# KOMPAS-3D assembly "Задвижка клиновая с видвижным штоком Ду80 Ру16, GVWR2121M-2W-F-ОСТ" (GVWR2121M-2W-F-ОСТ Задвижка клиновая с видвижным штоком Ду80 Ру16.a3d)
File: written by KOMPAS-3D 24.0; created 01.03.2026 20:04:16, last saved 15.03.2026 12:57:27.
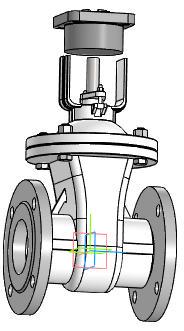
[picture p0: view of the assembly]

Document properties: Автор: R2D2; Полное имя файла: E:\Работа\Зайцев\GVWR2121M-2W-F-ОСТ Задвижка клиновая с видвижным штоком Ду50-300 Ру16\DN80\Исходные материалы\GVWR2121M-2W-F-ОСТ Задвижка клиновая с видвижным штоком Ду80 Ру16.a3d

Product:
- Component [detail]: AS 1110 - M12 x 45  | qty 4  | pos. 2  | Масса: 0.056439; Комментарий: Болты и винты   шестигранные точные   метрические ISO; Автор: R2D2; additional columns: Сталь, мягкая; source file: AS 1110 - M12 x 45 AS 1110 - M12 x 45.m3d
- Component [detail]: ANSI B18.2.4.2M - M12x1,75 - 18  | designation ANSI B18.2.4.2M - M12x1,75  | qty 4  | pos. 3  | Масса: 0.018772; Комментарий: Типы метрических   шестигранных гаек   2; Автор: R2D2; additional columns: Сталь, мягкая; source file: ANSI B18.2.4.2M - M12x1,75 ANSI B18.2.4.2M - M12x1,75 - 18.m3d
- Component [detail]: ANSI B18.2.4.2M - M5x0,8 - 8  | designation ANSI B18.2.4.2M - M5x0,8  | qty 2  | pos. 4  | Масса: 0.00167; Комментарий: Типы метрических   шестигранных гаек   2; Автор: R2D2; additional columns: Сталь, мягкая; source file: ANSI B18.2.4.2M - M5x0,8 ANSI B18.2.4.2M - M5x0,8 - 8.m3d
- Component [detail]: Деталь1  | qty 1  | pos. 5  | Масса: 23.507576; additional columns: Типовые; source file: 2.m3d
- Component [detail]: Фланец  | qty 2  | pos. 5  | Масса: 3.375667; Автор: R2D2; additional columns: Типовые; source file: Фланец DN80 PN16 b20.m3d
- Component [assembly]: DN50_3D_STEP  | designation Сборка  | qty 1  | pos. 6  | Масса: 2.725126; Автор: R2D2; source file: Фланец А.a3d
- Part/product: Задвижка клиновая с видвижным штоком Ду80 Ру16  | designation GVWR2121M-2W-F-ОСТ
    Масса: 23.996
    Раздел спецификации: Прочие изделия
    Примечание: D040-07878

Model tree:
1. Массив по концентрической сетке:1  (labels: Грань.Твердое тело1)  (4 pattern instances)
     Шаг 2 = 360
2. Массив по концентрической сетке:2  (with: Грань.Элемент вращения:1, Грань.Операция без истории:2)  (labels: Грань.Твердое тело1; Грань.Solid1)  (2 pattern instances)
     Шаг 2 = 360; Расстояние = -105; Ориентация = 2; Расстояние = -349

Referenced files in E:\Работа\Зайцев\GVWR2121M-2W-F-ОСТ Задвижка клиновая с видвижным штоком Ду50-300 Ру16\DN80\Исходные материалы\: AS 1110 - M12 x 45 AS 1110 - M12 x 45.m3d, ANSI B18.2.4.2M - M12x1,75 ANSI B18.2.4.2M - M12x1,75 - 18.m3d, ANSI B18.2.4.2M - M5x0,8 ANSI B18.2.4.2M - M5x0,8 - 8.m3d, 2.m3d, Фланец DN80 PN16 b20.m3d, Фланец А.a3d
Referenced files in E:\Работа\Зайцев\GVWR2626M-2W-F-S Задвижка клиновая с выдвижным штоком DN.ru Ду50-300 Ру16\DN80\исходные материалы\: Фланец DN80 PN16 b20.m3d
Referenced files in E:\Работа\Зайцев\GVWR3131M-2W-F-S Задвижка клиновая с выдвижным штоком DN.ru Ду50-200 Ру63\DN80\исходные материалы\: ANSI B18.2.4.2M - M12x1,75 ANSI B18.2.4.2M - M12x1,75 - 18.m3d, AS 1110 - M12 x 45 AS 1110 - M12 x 45.m3d, ANSI B18.2.4.2M - M5x0,8 ANSI B18.2.4.2M - M5x0,8 - 8.m3d
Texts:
  Программные изделия  и базы данных
  ANSI B18.2.4.2M - M12x1,75
  ANSI B18.2.4.2M - M5x0,8
  GVWR2121M-2W-F-ОСТ
  AS 1110 - M12 x 45 AS 1110 - M12 x 45 (1)
  ANSI B18.2.4.2M - M12x1,75 ANSI B18.2.4.2M - M12x1,75 - 18 (1)
  ANSI B18.2.4.2M - M5x0,8 ANSI B18.2.4.2M - M5x0,8 - 8 (1)
  Деталь1 Деталь1
  Фланец (1)
  Фланец (2)
  Сборка DN50_3D_STEP
  Ось Y.Начало координат
  Ось Z.Начало координат
  Плоскость ZX.Начало координат
  Плоскость XY.Начало координат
